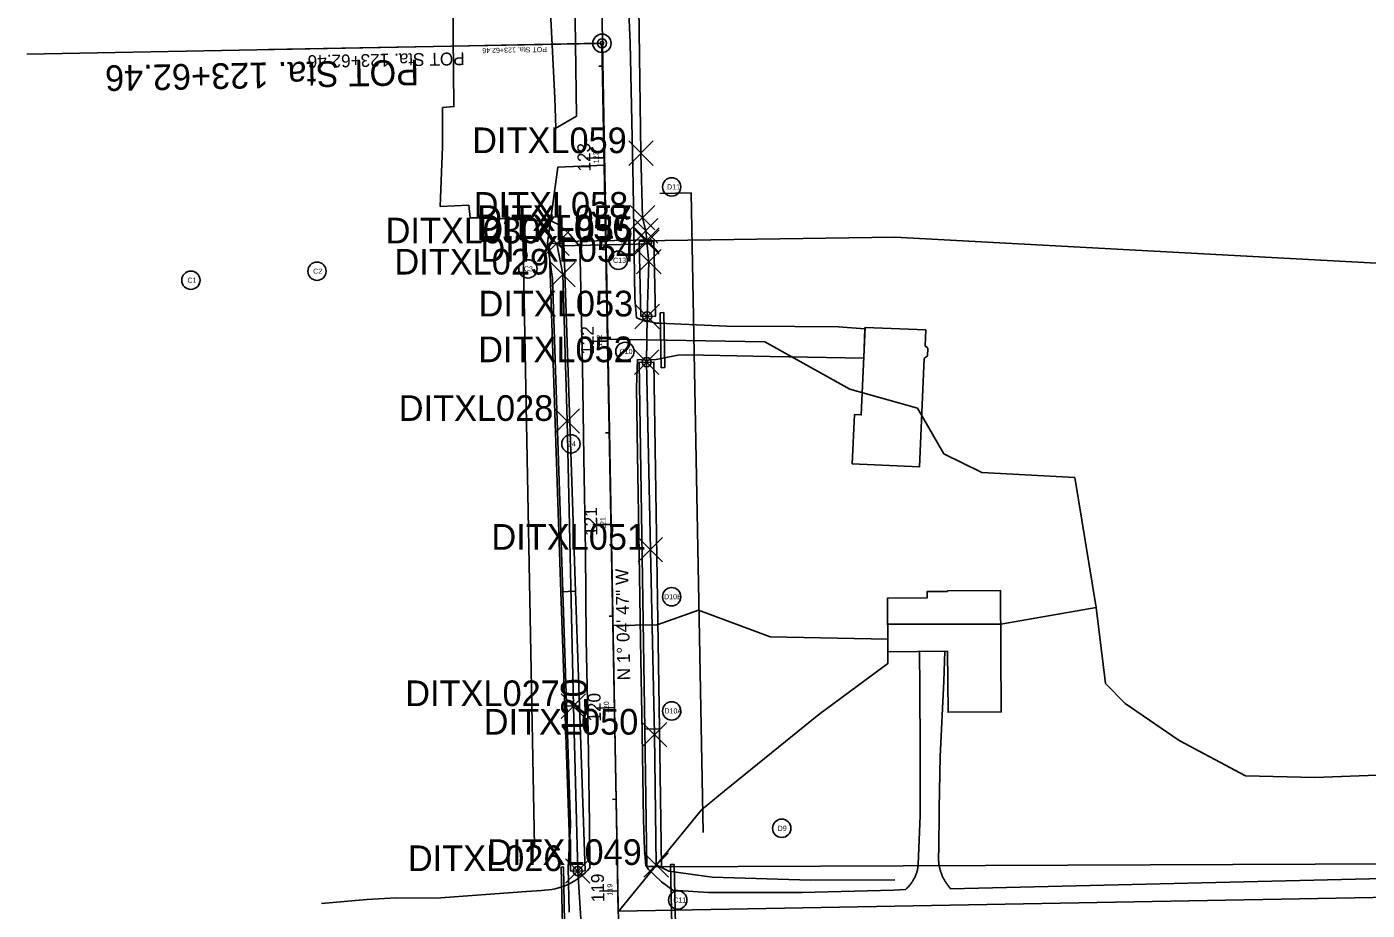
# Model space of a CAD drawing. Extents: x 2287043 to 2296348, y 637947 to 641293.
# Drawn here: x 2287043 to 2287774, y 639863 to 640344 of the extents above; entities that cross this region are included whole.
import ezdxf

# ---------------------------------------------------------------- set-up
doc = ezdxf.new("R2010")
doc.units = 0
for name, color, linetype in [('DR_P_Drainage_Area', 7, 'Continuous'), ('DR_P_Storm_Sewer', 7, 'Continuous'), ('GE_X_CL_100', 7, 'Continuous'), ('GE_X_CL_20', 7, 'Continuous'), ('GE_X_CL_50', 7, 'Continuous'), ('GK_Visualization', 7, 'Continuous'), ('RW_P_Prelim_RW', 7, 'Continuous'), ('SC_Scratch10', 7, 'Continuous'), ('SC_Scratch12', 7, 'Continuous'), ('SC_Scratch4', 7, 'Continuous'), ('SC_Scratch5', 7, 'Continuous'), ('SC_Scratch6', 7, 'Continuous'), ('SC_Scratch7', 7, 'Continuous'), ('SC_Scratch8', 7, 'Continuous'), ('SC_Scratch9', 7, 'Continuous')]:
    doc.layers.add(name, color=color, linetype=linetype)

msp = doc.modelspace()

# ---------------------------------------------------------------- linework, layer by layer
at = {"layer": 'DR_P_Drainage_Area'}
for p, q in [((2287357.3, 640335.57), (2287354.99, 640499.61)), ((2287365.99, 639861.68), (2287357.3, 640335.57)), ((2287360.26, 640173.94), (2287445.9, 640172.63)), ((2287574.51, 640018.53), (2287626.61, 640027.64)), ((2287387.13, 640018.22), (2287363.13, 640017.78)), ((2287512.93, 640018.53), (2287574.51, 640018.53)), ((2287338.73, 639885.77), (2287339.16, 639861.53))]:
    msp.add_line(p, q, dxfattribs=at)
for points in [[(2287358.52, 640268.92), (2287332.96, 640267.77), (2287327.41, 640226.35)], [(2287327.41, 640226.35), (2287330.14, 640207.01), (2287339.98, 639909.19), (2287338.73, 639885.77)], [(2287529.13, 640136.33), (2287492.32, 640146.67), (2287445.9, 640172.63)], [(2287529.13, 640136.33), (2287543.52, 640111.42), (2287564.16, 640101.35), (2287614.85, 640098.66)], [(2287626.61, 640027.64), (2287614.85, 640098.66)], [(2287626.61, 640027.64), (2287631.72, 639986.14), (2287642.32, 639975.29), (2287671.83, 639955.05)], [(2287387.13, 640018.22), (2287409.63, 640026.2), (2287448.71, 640011.6), (2287512.93, 640010.41)], [(2287512.93, 640018.53), (2287512.93, 640010.41)], [(2287671.83, 639955.05), (2287708.02, 639935.82), (2287745.84, 639934.88), (2287823.23, 639937.76), (2287844.24, 639944.37), (2287857.82, 639965.11), (2287870.83, 639988.53)], [(2287366.31, 639862.01), (2287948.06, 639872.57), (2287973.81, 639872.7), (2287999.81, 639872.01), (2288025.56, 639870.64), (2288051.56, 639868.51), (2288077.31, 639865.64), (2288102.81, 639862.01), (2288128.31, 639857.64), (2288153.81, 639852.57), (2288179.06, 639846.76), (2288204.06, 639840.2), (2288229.06, 639833.64), (2288254.31, 639827.76), (2288279.81, 639822.7), (2288305.31, 639818.26), (2288331.06, 639814.64), (2288356.81, 639811.7), (2288382.56, 639809.57), (2288408.31, 639808.14), (2288412.26, 639808.03)]]:
    msp.add_lwpolyline(points, dxfattribs=at)
at = {"layer": 'DR_P_Storm_Sewer'}
for p, q in [((2287334.12, 640227.25), (2287384.11, 640228.19)), ((2287334.16, 640225), (2287334.12, 640227.25)), ((2287334.16, 640225), (2287384.15, 640225.94)), ((2287384.15, 640225.94), (2287384.11, 640228.19)), ((2287388.86, 640188.46), (2287390.86, 640188.5)), ((2287389.42, 640158.47), (2287388.86, 640188.46)), ((2287391.42, 640158.5), (2287390.86, 640188.5)), ((2287389.42, 640158.47), (2287391.42, 640158.5)), ((2287334.92, 639886.1), (2287336.17, 639886.13)), ((2287335.86, 639836.11), (2287334.92, 639886.1)), ((2287337.11, 639836.14), (2287336.17, 639886.13)), ((2287394.53, 639887.53), (2287396.53, 639887.56)), ((2287395.47, 639837.54), (2287394.53, 639887.53)), ((2287397.47, 639837.57), (2287396.53, 639887.56))]:
    msp.add_line(p, q, dxfattribs=at)
at = {"layer": 'GE_X_CL_100'}
for p, q in [((2287352.08, 640335.33), (2287043.48, 640329.51)), ((2287401.6, 637973.38), (2287357.08, 640335.42)), ((2287358.26, 640272.97), (2287348.26, 640272.79)), ((2287360.14, 640172.99), (2287350.14, 640172.8)), ((2287362.03, 640073.01), (2287352.03, 640072.82)), ((2287363.91, 639973.03), (2287353.91, 639972.84)), ((2287365.8, 639873.04), (2287355.8, 639872.86))]:
    msp.add_line(p, q, dxfattribs=at)
msp.add_circle((2287357.08, 640335.42), 5, dxfattribs=at)
at = {"layer": 'GE_X_CL_20'}
for p, q in [((2287356.08, 640335.4), (2287284.36, 640334.05)), ((2287401.6, 637973.38), (2287357.08, 640335.42)), ((2287357.32, 640322.96), (2287355.32, 640322.93)), ((2287358.26, 640272.97), (2287356.26, 640272.94)), ((2287359.2, 640222.98), (2287357.2, 640222.94)), ((2287360.14, 640172.99), (2287358.14, 640172.95)), ((2287361.09, 640123), (2287359.09, 640122.96)), ((2287362.03, 640073.01), (2287360.03, 640072.97)), ((2287362.97, 640023.02), (2287360.97, 640022.98)), ((2287363.91, 639973.03), (2287361.91, 639972.99)), ((2287364.85, 639923.04), (2287362.85, 639923)), ((2287365.8, 639873.04), (2287363.8, 639873.01))]:
    msp.add_line(p, q, dxfattribs=at)
msp.add_circle((2287357.08, 640335.42), 1, dxfattribs=at)
at = {"layer": 'GE_X_CL_50'}
for p, q in [((2287354.58, 640335.37), (2287175.29, 640331.99)), ((2287354.58, 640335.37), (2287175.29, 640331.99)), ((2287401.6, 637973.38), (2287357.08, 640335.42)), ((2287358.26, 640272.97), (2287353.26, 640272.88)), ((2287358.26, 640272.97), (2287353.26, 640272.88)), ((2287360.14, 640172.99), (2287355.14, 640172.9)), ((2287360.14, 640172.99), (2287355.14, 640172.9)), ((2287362.03, 640073.01), (2287357.03, 640072.91)), ((2287362.03, 640073.01), (2287357.03, 640072.91)), ((2287363.91, 639973.03), (2287358.91, 639972.93)), ((2287363.91, 639973.03), (2287358.91, 639972.93)), ((2287365.8, 639873.04), (2287360.8, 639872.95)), ((2287365.8, 639873.04), (2287360.8, 639872.95))]:
    msp.add_line(p, q, dxfattribs=at)
msp.add_circle((2287357.08, 640335.42), 2.5, dxfattribs=at)
msp.add_circle((2287357.08, 640335.42), 2.5, dxfattribs=at)
at = {"layer": 'GK_Visualization'}
for p, q in [((2287378.35, 640275.48), (2287377.14, 640355.07)), ((2287371.68, 640268.8), (2287385.01, 640282.15)), ((2287371.68, 640282.15), (2287385.01, 640268.8)), ((2287379.18, 640240.28), (2287378.35, 640275.48)), ((2287372.52, 640233.6), (2287385.85, 640246.95)), ((2287372.52, 640246.95), (2287385.85, 640233.6)), ((2287374.29, 640226.43), (2287387.62, 640239.78)), ((2287374.29, 640239.78), (2287387.62, 640226.43)), ((2287380.95, 640233.1), (2287379.18, 640240.28)), ((2287325.84, 640219.61), (2287339.17, 640232.96)), ((2287325.84, 640232.96), (2287339.17, 640219.61)), ((2287374.86, 640221.32), (2287388.2, 640234.67)), ((2287374.86, 640234.67), (2287388.2, 640221.32)), ((2287374.97, 640220.32), (2287388.3, 640233.67)), ((2287374.97, 640233.67), (2287388.3, 640220.32)), ((2287381.53, 640227.99), (2287380.95, 640233.1)), ((2287335.76, 640209.29), (2287332.51, 640226.28)), ((2287382.65, 640216.28), (2287381.63, 640227)), ((2287375.98, 640209.61), (2287389.31, 640222.96)), ((2287375.98, 640222.96), (2287389.31, 640209.61)), ((2287329.09, 640202.62), (2287342.42, 640215.97)), ((2287329.09, 640215.97), (2287342.42, 640202.62)), ((2287381.72, 640186.43), (2287382.65, 640216.28)), ((2287338.09, 640129.44), (2287335.76, 640209.29)), ((2287375.06, 640179.75), (2287388.39, 640193.1)), ((2287375.06, 640193.1), (2287388.39, 640179.75)), ((2287381.42, 640161.46), (2287381.72, 640186.43)), ((2287374.75, 640154.78), (2287388.09, 640168.13)), ((2287374.75, 640168.13), (2287388.09, 640154.78)), ((2287383.49, 640059.18), (2287381.42, 640161.46)), ((2287331.42, 640122.76), (2287344.75, 640136.11)), ((2287331.42, 640136.11), (2287344.75, 640122.76)), ((2287341.52, 639973.87), (2287338.09, 640129.44)), ((2287376.83, 640052.51), (2287390.16, 640065.86)), ((2287376.83, 640065.86), (2287390.16, 640052.51)), ((2287385.75, 639958.32), (2287383.49, 640059.18)), ((2287334.85, 639967.2), (2287348.18, 639980.55)), ((2287334.85, 639980.55), (2287348.18, 639967.2)), ((2287343.84, 639883.89), (2287341.52, 639973.87)), ((2287379.09, 639951.64), (2287392.42, 639964.99)), ((2287379.09, 639964.99), (2287392.42, 639951.64)), ((2287386.65, 639887.24), (2287385.75, 639958.32)), ((2287337.17, 639877.21), (2287350.51, 639890.56)), ((2287337.17, 639890.56), (2287350.51, 639877.21)), ((2287379.99, 639880.57), (2287393.32, 639893.92)), ((2287379.99, 639893.92), (2287393.32, 639880.57)), ((2287346.67, 639840.44), (2287343.84, 639883.89))]:
    msp.add_line(p, q, dxfattribs=at)
at = {"layer": 'RW_P_Prelim_RW'}
for p, q in [((2287405.63, 640253.86), (2287388.63, 640253.54)), ((2287412.2, 639905), (2287405.63, 640253.86)), ((2287320.33, 639897.36), (2287313.98, 640234.1))]:
    msp.add_line(p, q, dxfattribs=at)
at = {"layer": 'SC_Scratch10'}
for points in [[(2287334.67, 640036.25), (2287328.22, 640226.14), (2287336.22, 640226.42), (2287342.66, 640036.52)], [(2287339.84, 639883.76), (2287336.79, 639973.79), (2287344.78, 639974.06), (2287347.84, 639884.03)], [(2287381.49, 639886.34), (2287380.38, 639961.33), (2287388.38, 639961.45), (2287389.49, 639886.45)]]:
    msp.add_lwpolyline(points, close=True, dxfattribs=at)
at = {"layer": 'SC_Scratch12'}
msp.add_lwpolyline([(2287512.93, 640010.41), (2287512.93, 639997.11), (2287475.4, 639969.32), (2287423.8, 639927.42), (2287411.29, 639917.27), (2287365.99, 639861.68)], dxfattribs=at)
at = {"layer": 'SC_Scratch4'}
for p, q in [((2287342.63, 640335.31), (2287339.95, 640565.88)), ((2287363.81, 640530.27), (2287372.48, 640335.71)), ((2287331.43, 640305.7), (2287329.09, 640352.44)), ((2287372.48, 640335.71), (2287373.66, 640275.42)), ((2287500.49, 640179.75), (2287499.79, 640163.58)), ((2287530.29, 640003.68), (2287543.99, 640003.76)), ((2287516.1, 639873.57), (2287522.66, 639873.93)), ((2287547.17, 639874.27), (2287798.65, 639880.2))]:
    msp.add_line(p, q, dxfattribs=at)
for points in [[(2287284.57, 640247.19), (2287268.9, 640246.45), (2287270.15, 640278.98), (2287270.2, 640300.37), (2287276.32, 640300.86), (2287275.93, 640339.7), (2287275.97, 640369.4), (2287277.25, 640399.95), (2287276.62, 640425.18), (2287275.79, 640457.99), (2287275.88, 640491.85), (2287276.31, 640523.32), (2287276.98, 640560.61), (2287290.08, 640568.15), (2287290.42, 640581.97), (2287258, 640583.22), (2287225.17, 640584.67), (2287199.3, 640585.49), (2287190.26, 640585.71)], [(2287342.63, 640335.31), (2287343.2, 640295.63), (2287331.96, 640289.04), (2287331.43, 640305.7)], [(2287375.86, 640185.74), (2287375.05, 640196.62), (2287374.03, 640258.29), (2287373.66, 640275.42)], [(2287329.64, 640238.31), (2287328.2, 640238.64), (2287319.78, 640238.78), (2287308.42, 640239.45), (2287295.72, 640239.94), (2287290.34, 640240.21), (2287285.14, 640240.18), (2287284.57, 640247.19)], [(2287344.93, 640224.57), (2287339.65, 640231.13), (2287334.07, 640236.28), (2287329.64, 640238.31)], [(2287344.93, 640224.57), (2287344.93, 640224.57), (2287345.36, 640209.89), (2287346.52, 640159.11), (2287347.25, 640109.22), (2287348.05, 640058.4), (2287348.5, 640010.24), (2287349.55, 639958.93), (2287350.28, 639909.65), (2287350.51, 639885.62)], [(2287380.68, 640183.8), (2287375.86, 640185.74)], [(2287386.48, 640182.82), (2287384.61, 640183.31), (2287380.68, 640183.8)], [(2287386.48, 640182.82), (2287387.71, 640182.72), (2287388.27, 640182.69)], [(2287388.27, 640182.69), (2287424.95, 640181.18), (2287462.24, 640180.93), (2287486.13, 640180.71), (2287500.49, 640179.75)], [(2287516.1, 639873.57), (2287466.17, 639872.28), (2287415.1, 639872.18), (2287395.67, 639873.46), (2287389.58, 639877.99), (2287382.39, 639884.73), (2287380.96, 639886.95), (2287380.28, 639895.47), (2287379.78, 639911.89), (2287378.97, 639959.08), (2287378.17, 640009.74), (2287377.33, 640056.87), (2287376.4, 640111.19), (2287375.94, 640147.61), (2287376.38, 640162.86)], [(2287376.38, 640162.86), (2287380.88, 640162.59)], [(2287380.88, 640162.59), (2287386.6, 640162.88), (2287398.38, 640165.35)], [(2287499.79, 640163.58), (2287448.84, 640164.66), (2287403.34, 640165.44), (2287398.38, 640165.35)], [(2287529.55, 639887.52), (2287530.56, 639914.12), (2287530.52, 639950.47), (2287530.41, 639983.59), (2287530.29, 640003.68)], [(2287543.99, 640003.76), (2287543.45, 639987.5), (2287541.48, 639946.45), (2287540.9, 639918.19), (2287540.68, 639894.2)], [(2287540.68, 639894.2), (2287540.64, 639893.76), (2287540.6, 639893.33), (2287540.58, 639892.89), (2287540.56, 639892.45), (2287540.54, 639892), (2287540.54, 639891.56), (2287540.54, 639891.12), (2287540.55, 639890.68), (2287540.57, 639890.24), (2287540.59, 639889.8), (2287540.63, 639889.36), (2287540.67, 639888.92), (2287540.71, 639888.49), (2287540.77, 639888.05), (2287540.83, 639887.61), (2287540.9, 639887.18), (2287540.98, 639886.74), (2287541.06, 639886.31), (2287541.16, 639885.88), (2287541.26, 639885.45), (2287541.36, 639885.02), (2287541.48, 639884.6), (2287541.6, 639884.18), (2287541.73, 639883.75), (2287541.87, 639883.34), (2287542.01, 639882.92), (2287542.16, 639882.5), (2287542.32, 639882.09), (2287542.48, 639881.68), (2287542.66, 639881.28), (2287542.83, 639880.88), (2287543.02, 639880.48), (2287543.21, 639880.08), (2287543.41, 639879.69), (2287543.62, 639879.3), (2287543.83, 639878.91), (2287544.05, 639878.53), (2287544.28, 639878.15), (2287544.51, 639877.78), (2287544.75, 639877.41), (2287544.99, 639877.04), (2287545.24, 639876.68), (2287545.5, 639876.32), (2287545.76, 639875.97), (2287546.03, 639875.62), (2287546.31, 639875.28), (2287546.59, 639874.94), (2287546.88, 639874.6), (2287547.17, 639874.27)], [(2287350.51, 639885.62), (2287350.51, 639885.62)], [(2287522.66, 639873.93), (2287522.92, 639874.16), (2287523.18, 639874.4), (2287523.43, 639874.64), (2287523.68, 639874.88), (2287523.92, 639875.13), (2287524.16, 639875.38), (2287524.39, 639875.63), (2287524.62, 639875.89), (2287524.85, 639876.16), (2287525.07, 639876.43), (2287525.29, 639876.7), (2287525.5, 639876.97), (2287525.71, 639877.25), (2287525.91, 639877.53), (2287526.11, 639877.82), (2287526.3, 639878.11), (2287526.49, 639878.4), (2287526.67, 639878.69), (2287526.85, 639878.99), (2287527.02, 639879.29), (2287527.19, 639879.6), (2287527.35, 639879.9), (2287527.51, 639880.21), (2287527.66, 639880.52), (2287527.81, 639880.84), (2287527.95, 639881.16), (2287528.08, 639881.48), (2287528.21, 639881.8), (2287528.34, 639882.12), (2287528.46, 639882.45), (2287528.57, 639882.78), (2287528.68, 639883.11), (2287528.78, 639883.44), (2287528.88, 639883.77), (2287528.97, 639884.11), (2287529.05, 639884.44), (2287529.13, 639884.78), (2287529.2, 639885.12), (2287529.27, 639885.46), (2287529.33, 639885.8), (2287529.39, 639886.14), (2287529.44, 639886.49), (2287529.48, 639886.83), (2287529.52, 639887.18), (2287529.55, 639887.52)], [(2287324.1, 639873.34), (2287315.92, 639872.77), (2287266.62, 639869.18), (2287244.81, 639869.29), (2287228.95, 639868.43), (2287204.24, 639866.17)], [(2287324.1, 639873.34), (2287315.92, 639872.77), (2287266.62, 639869.18), (2287244.81, 639869.29), (2287228.95, 639868.43), (2287204.24, 639866.17)]]:
    msp.add_lwpolyline(points, dxfattribs=at)
msp.add_arc((2287323.6, 639908.92), 35.59, 270.80468, 319.10835, dxfattribs=at)
msp.add_arc((2287323.6, 639908.92), 35.59, 270.80468, 319.10835, dxfattribs=at)
at = {"layer": 'SC_Scratch5'}
for points in [[(2287533.63, 640179.03), (2287533.25, 640170.34), (2287534.67, 640169.09), (2287534.49, 640164.9), (2287532.76, 640163.51), (2287530.2, 640104.38), (2287493.55, 640105.97), (2287494.72, 640132.87), (2287498.45, 640132.71), (2287500.52, 640180.47)], [(2287512.95, 640003.57), (2287512.76, 640032.74), (2287534.35, 640032.88), (2287534.32, 640036.32), (2287545.43, 640036.39), (2287545.42, 640036.72), (2287574.39, 640036.9), (2287574.81, 639970.74), (2287545.77, 639970.56), (2287545.56, 640003.77)]]:
    msp.add_lwpolyline(points, close=True, dxfattribs=at)
at = {"layer": 'SC_Scratch6'}
msp.add_line((2287815.82, 639888), (2287386.48, 639886.29), dxfattribs=at)
msp.add_lwpolyline([(2287378.87, 640227.75), (2287516.76, 640229.61), (2287870.19, 640210.65), (2288138.22, 640270.42), (2288371.69, 640288.3), (2289483.72, 640231.09)], dxfattribs=at)
at = {"layer": 'SC_Scratch7'}
for points in [[(2287381.53, 640227.99), (2287380.95, 640233.1), (2287379.18, 640240.28), (2287378.35, 640275.48), (2287377.14, 640355.07)], [(2287352.98, 639418.42), (2287351.79, 639473.08), (2287349.85, 639562.67), (2287348.14, 639641.39), (2287344.9, 639812.9), (2287346.67, 639840.44), (2287343.84, 639883.89), (2287341.52, 639973.87), (2287338.09, 640129.44), (2287335.76, 640209.29), (2287332.51, 640226.28)], [(2287386.65, 639887.24), (2287385.75, 639958.32), (2287383.49, 640059.18), (2287381.42, 640161.46), (2287381.72, 640186.43), (2287382.65, 640216.28), (2287381.63, 640227)], [(2287386.65, 639887.24), (2287393.57, 639883.83), (2287417.16, 639880.52), (2287471.05, 639878.95), (2287516.73, 639879.15)]]:
    msp.add_lwpolyline(points, dxfattribs=at)
for centre in [(2287381.72, 640186.43), (2287381.42, 640161.46), (2287343.84, 639883.89)]:
    msp.add_circle(centre, 2.5, dxfattribs=at)
at = {"layer": 'SC_Scratch8'}
for centre in [(2287395.09, 640257.07), (2287365.98, 640217.04), (2287132.93, 640206.18), (2287201.7, 640211.1), (2287316.69, 640212.37), (2287369.62, 640167.32), (2287340.15, 640116.93), (2287395.09, 640033.51), (2287395.09, 639971.26), (2287455.12, 639907.22), (2287398.42, 639868.1)]:
    msp.add_circle(centre, 5, dxfattribs=at)
at = {"layer": 'SC_Scratch9'}
for points in [[(2287378.3, 640186.41), (2287377.42, 640227.26), (2287385.42, 640227.43), (2287386.29, 640186.59)], [(2287380.38, 639961.33), (2287377.42, 640161.38), (2287385.42, 640161.5), (2287388.38, 639961.45)], [(2287336.79, 639973.79), (2287334.67, 640036.25), (2287342.66, 640036.52), (2287344.78, 639974.06)]]:
    msp.add_lwpolyline(points, close=True, dxfattribs=at)

# ---------------------------------------------------------------- texts
at = {"layer": 'GE_X_CL_100'}
for s, rotation, p in [('POT Sta. 123+62.46', 181.07978, (2287257.23, 640326.54)), ('120', 91.07978, (2287349.19, 639957.92))]:
    msp.add_text(s, height=14, rotation=rotation, dxfattribs=at).set_placement(p)
at = {"layer": 'GE_X_CL_20'}
for s, rotation, p in [('POT Sta. 123+62.46', 181.07978, (2287327.11, 640333.45)), ('123', 91.07978, (2287355.31, 640269.99)), ('122', 91.07978, (2287357.2, 640170.04)), ('121', 91.07978, (2287359.07, 640070.52)), ('120', 91.07978, (2287360.97, 639970.01)), ('119', 91.07978, (2287362.84, 639870.61))]:
    msp.add_text(s, height=2.8, rotation=rotation, dxfattribs=at).set_placement(p)
at = {"layer": 'GE_X_CL_50'}
for s, rotation, p in [('POT Sta. 123+62.46', 181.07978, (2287282.16, 640330.51)), ('POT Sta. 123+62.46', 181.07978, (2287282.16, 640330.51)), ('123', 91.07978, (2287350.9, 640265.5)), ('123', 91.07978, (2287350.9, 640265.5)), ('122', 91.07978, (2287352.78, 640165.61)), ('122', 91.07978, (2287352.78, 640165.61)), ('121', 91.07978, (2287354.64, 640066.79)), ('121', 91.07978, (2287354.64, 640066.79)), ('N 1%%d 04\' 47" W', 91.07978, (2287372.54, 639988)), ('120', 91.07978, (2287356.55, 639965.48)), ('120', 91.07978, (2287356.55, 639965.48)), ('119', 91.07978, (2287358.41, 639866.96)), ('119', 91.07978, (2287358.41, 639866.96))]:
    msp.add_text(s, height=7, rotation=rotation, dxfattribs=at).set_placement(p)
at = {"layer": 'GK_Visualization'}
for s, p in [('DITXL059', (2287286.31, 640275.48)), ('DITXL058', (2287287.14, 640240.28)), ('DITXL057', (2287289.03, 640233.1)), ('DITXL030', (2287239.14, 640226.28)), ('DITXL056', (2287288.72, 640227.99)), ('DITXL055', (2287289.71, 640227)), ('DITXL054', (2287290.83, 640216.28)), ('DITXL029', (2287243.94, 640209.29)), ('DITXL053', (2287289.79, 640186.43)), ('DITXL052', (2287289.6, 640161.46)), ('DITXL028', (2287246.27, 640129.44)), ('DITXL051', (2287296.83, 640059.18)), ('DITXL027', (2287249.81, 639973.87)), ('DITXL050', (2287292.61, 639958.32)), ('DITXL026', (2287251.25, 639883.89)), ('DITXL049', (2287294.51, 639887.24))]:
    msp.add_text(s, height=14, dxfattribs=at).set_placement(p)
at = {"layer": 'SC_Scratch8'}
for s, p in [('D11', (2287392.55, 640255.67)), ('C13', (2287363.13, 640215.64)), ('C2', (2287199.59, 640209.7)), ('C3', (2287314.5, 640210.97)), ('C1', (2287131.07, 640204.78)), ('C10', (2287366.64, 640165.92)), ('D4', (2287337.9, 640115.53)), ('D10B', (2287390.91, 640032.11)), ('D10A', (2287391.13, 639969.86)), ('D9', (2287452.91, 639905.82)), ('C11', (2287395.9, 639866.7))]:
    msp.add_text(s, height=2.8, dxfattribs=at).set_placement(p)

doc.saveas('drawing.dxf')
